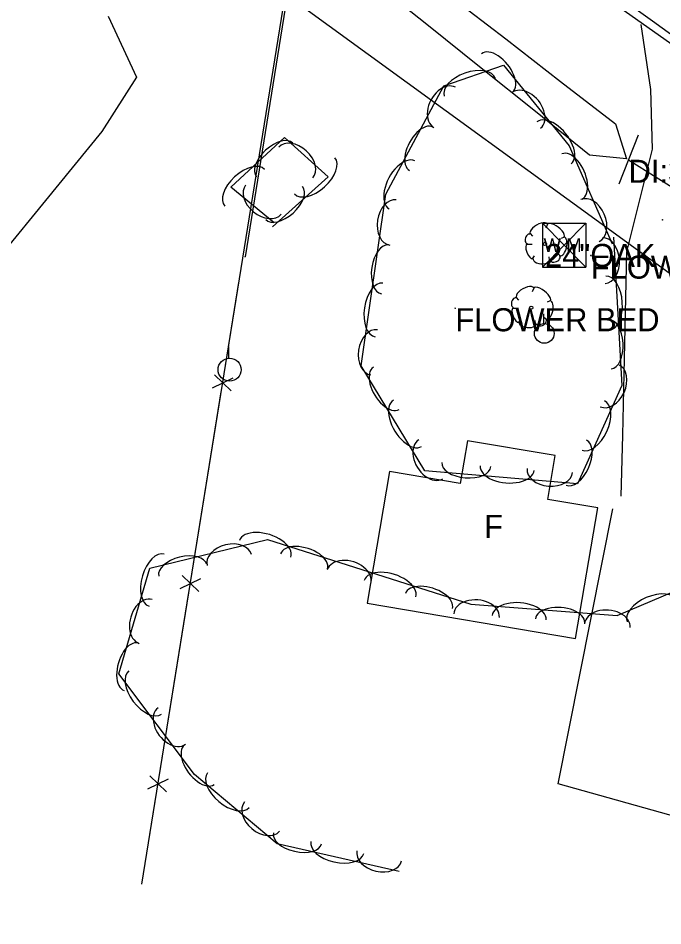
# Model space of a CAD drawing. Extents: x 1441650 to 1491889, y 345904 to 358319.
# Drawn here: x 1444980.2 to 1445119.8, y 354726 to 354922.6 of the extents above; entities that cross this region are included whole.
import ezdxf

# ---------------------------------------------------------------- set-up
doc = ezdxf.new("R2010")
doc.units = 0
for name, color, linetype in [('S_BUILDING', 7, 'Continuous'), ('S_BUILDING_ANNOT', 7, 'Continuous'), ('S_CROSS_DRAIN', 7, 'Continuous'), ('S_CROSS_DRAIN_ANNOT', 7, 'Continuous'), ('S_DITCHLINE', 7, 'Continuous'), ('S_DRG_PT_SYM', 7, 'Continuous'), ('S_EDGE_PAVEMENT', 7, 'Continuous'), ('S_FENCE', 7, 'Continuous'), ('S_GRAVEL_ROAD', 7, 'Continuous'), ('S_HEADWALL', 7, 'Continuous'), ('S_MSC_PT_SYM', 7, 'Continuous'), ('S_PARKING', 7, 'Continuous'), ('S_SHOULDER', 7, 'Continuous'), ('S_SURVEY_TEXT_ANNOT', 7, 'Continuous'), ('S_TREE', 7, 'Continuous'), ('S_TREE_ANNOT', 7, 'Continuous'), ('S_UTILITY_POLE', 7, 'Continuous'), ('S_WATER_UTILITIES', 7, 'Continuous')]:
    doc.layers.add(name, color=color, linetype=linetype)

msp = doc.modelspace()

# ---------------------------------------------------------------- linework, layer by layer
at = {"layer": 'S_BUILDING'}
msp.add_lwpolyline([(1445055.73, 354795.89), (1445100.88, 354788.24), (1445105.67, 354816.5), (1445094.84, 354818.33), (1445096.45, 354827.85), (1445077.43, 354831.07), (1445075.86, 354821.83), (1445060.56, 354824.42)], close=True, dxfattribs=at)
at = {"layer": 'S_CROSS_DRAIN'}
msp.add_line((1445112.33, 354891.94), (1445133.79, 354878.46), dxfattribs=at)
at = {"layer": 'S_DITCHLINE'}
msp.add_lwpolyline([(1445005.46, 354969.81), (1445018.13, 354968.56), (1445029.08, 354960.54), (1445040.03, 354952.52), (1445050.98, 354944.51), (1445061.93, 354936.49), (1445073.83, 354927.31), (1445085.73, 354918.12), (1445097.63, 354908.93), (1445109.52, 354899.75), (1445111.86, 354892.16), (1445103.9, 354892.94), (1445092.16, 354902.36), (1445080.42, 354911.79), (1445068.67, 354921.21), (1445056.93, 354930.63), (1445044.62, 354939.04), (1445032.31, 354947.45), (1445020, 354955.86), (1445007.69, 354964.27)], close=True, dxfattribs=at)
at = {"layer": 'S_DRG_PT_SYM'}
msp.add_lwpolyline([(1445112.33, 354891.94), (1445112.33, 354891.99), (1445112.33, 354891.94), (1445112.28, 354891.94), (1445112.33, 354891.94), (1445112.33, 354891.89), (1445112.33, 354891.94), (1445112.38, 354891.94)], dxfattribs=at)
at = {"layer": 'S_EDGE_PAVEMENT'}
msp.add_lwpolyline([(1445104.48, 354931.44), (1445117.54, 354922.02), (1445130.6, 354912.6), (1445144.39, 354902.99), (1445158.18, 354893.39), (1445171.35, 354884.38), (1445184.53, 354875.37), (1445198.09, 354866.37), (1445211.64, 354857.38), (1445224.35, 354849.14), (1445237.06, 354840.89), (1445251.76, 354831.71), (1445266.45, 354822.53), (1445278.03, 354815.47), (1445289.61, 354808.41)], dxfattribs=at)
at = {"layer": 'S_FENCE'}
for p, q in [((1445038.73, 354929.41), (1445029.31, 354870.93)), ((1445026.27, 354841.86), (1445022.68, 354845.34)), ((1445022.23, 354842.51), (1445026.72, 354844.69)), ((1445019.27, 354798.42), (1445015.68, 354801.9)), ((1445015.23, 354799.07), (1445019.73, 354801.25)), ((1445008.23, 354755.63), (1445012.73, 354757.81)), ((1445012.27, 354754.98), (1445008.68, 354758.46))]:
    msp.add_line(p, q, dxfattribs=at)
for points in [[(1445006.98, 354735), (1445038.28, 354929.3), (1444995.84, 354965.72)], [(1445024.79, 354845.58), (1445027.98, 354865.32)], [(1445020.98, 354821.88), (1445024.16, 354841.63)], [(1445017.79, 354802.14), (1445020.98, 354821.88)], [(1445013.98, 354778.44), (1445017.16, 354798.19)], [(1445010.8, 354758.69), (1445013.98, 354778.44)], [(1445006.98, 354735), (1445010.16, 354754.74)]]:
    msp.add_lwpolyline(points, dxfattribs=at)
at = {"layer": 'S_GRAVEL_ROAD'}
msp.add_lwpolyline([(1445115.02, 354921.26), (1445117.08, 354907.14), (1445117.45, 354894.22), (1445111.91, 354872.02), (1445111.61, 354858.78), (1445111.3, 354845.54), (1445110.99, 354832.3), (1445110.69, 354819.06)], dxfattribs=at)
at = {"layer": 'S_HEADWALL'}
msp.add_lwpolyline([(1445114.43, 354897.29), (1445110.26, 354886.62)], dxfattribs=at)
at = {"layer": 'S_MSC_PT_SYM'}
for points in [[(1445119.65, 354878.93), (1445119.65, 354878.98), (1445119.65, 354878.93), (1445119.6, 354878.93), (1445119.65, 354878.93), (1445119.65, 354878.88), (1445119.65, 354878.93), (1445119.7, 354878.93)], [(1445029.31, 354870.93), (1445029.31, 354870.98), (1445029.31, 354870.93), (1445029.26, 354870.93), (1445029.31, 354870.93), (1445029.31, 354870.88), (1445029.31, 354870.93), (1445029.36, 354870.93)], [(1445104.15, 354871.18), (1445104.15, 354871.23), (1445104.15, 354871.18), (1445104.1, 354871.18), (1445104.15, 354871.18), (1445104.15, 354871.13), (1445104.15, 354871.18), (1445104.2, 354871.18)], [(1445074.83, 354859.78), (1445074.83, 354859.83), (1445074.83, 354859.78), (1445074.78, 354859.78), (1445074.83, 354859.78), (1445074.83, 354859.73), (1445074.83, 354859.78), (1445074.88, 354859.78)]]:
    msp.add_lwpolyline(points, dxfattribs=at)
at = {"layer": 'S_PARKING'}
for points in [[(1444999.65, 354923.06), (1445005.79, 354909.82), (1444998.31, 354898.06), (1444964.51, 354856.77), (1444945.11, 354827.14), (1444930.71, 354797.81)], [(1445126.52, 354815.76), (1445124.68, 354754.11), (1445124.67, 354749.01), (1445097.1, 354756.74), (1445108.92, 354816.29)]]:
    msp.add_lwpolyline(points, dxfattribs=at)
at = {"layer": 'S_SHOULDER'}
msp.add_lwpolyline([(1445103.05, 354930.2), (1445116.32, 354920.82), (1445129.59, 354911.44), (1445143.44, 354901.68), (1445157.3, 354891.92), (1445170.43, 354883.05), (1445183.57, 354874.18), (1445197.06, 354865.12), (1445210.55, 354856.07), (1445223.33, 354847.89), (1445236.12, 354839.71), (1445250.59, 354830.39), (1445265.05, 354821.07), (1445276.89, 354813.98), (1445288.72, 354806.89)], dxfattribs=at)
at = {"layer": 'S_TREE'}
for p, q in [((1445094.8, 354877.96), (1445094.42, 354877.1)), ((1445091.01, 354875.94), (1445091.51, 354875.36)), ((1445098.37, 354875.17), (1445097.71, 354874.9)), ((1445090.35, 354873.62), (1445091.47, 354873.62)), ((1445091.51, 354870.44), (1445091.97, 354871.14)), ((1445095.19, 354870.17), (1445095.11, 354870.94)), ((1445097.59, 354871.06), (1445097.13, 354871.49)), ((1445091.82, 354864.14), (1445091.43, 354863.29)), ((1445088.02, 354862.12), (1445088.53, 354861.54)), ((1445095.39, 354861.35), (1445094.73, 354861.08)), ((1445087.36, 354859.8), (1445088.49, 354859.8)), ((1445088.53, 354856.62), (1445088.99, 354857.32)), ((1445092.21, 354856.35), (1445092.13, 354857.12)), ((1445094.61, 354857.24), (1445094.15, 354857.67))]:
    msp.add_line(p, q, dxfattribs=at)
for points in [[(1445109.05, 354875.17), (1445110.91, 354843.01), (1445101.26, 354821.71), (1445068.25, 354824.55), (1445054.43, 354847.27), (1445059.82, 354884.49), (1445072.33, 354907.95), (1445085.26, 354912.43), (1445099.47, 354894.94), (1445108.78, 354873.74)], [(1445035.58, 354878.3), (1445026.23, 354885.99), (1445037.86, 354896.75), (1445047.27, 354888.22), (1445035.25, 354877.43)], [(1445062.66, 354737.7), (1445036.25, 354743.75), (1445018.34, 354758.77), (1445002, 354780.57), (1445008.72, 354803.48), (1445034.19, 354809.69), (1445078.19, 354795.67), (1445109.88, 354793.21), (1445132.32, 354802.76), (1445141.03, 354825.37), (1445149.69, 354845.03), (1445168.23, 354849.09), (1445178.41, 354829.92), (1445171.6, 354792.55), (1445175.47, 354753.75), (1445190.97, 354727.66), (1445216.54, 354694.19), (1445235.93, 354674.69), (1445255.34, 354667.34), (1445272.22, 354672.85), (1445290.88, 354695.22)]]:
    msp.add_lwpolyline(points, dxfattribs=at)
for centre in [(1445094.24, 354873.71), (1445091.26, 354859.89)]:
    msp.add_circle(centre, 0.341, dxfattribs=at)
for centre, major_axis, ratio, start_param, end_param in [((1445083.88, 354910.77), (-3.37, 4.15), 0.540791, 3.141474, 6.283067), ((1445077.97, 354907.66), (-5.54, -1.92), 0.550022, 3.141593, 6.283185), ((1445072.54, 354903.28), (-2.33, -4.37), 0.685178, 3.141644, 6.283237), ((1445090.17, 354902.61), (-3.13, 3.84), 0.685427, 3.141392, 6.282985), ((1445096.21, 354895.59), (-3.7, 4.55), 0.550173, 3.14147, 6.283063), ((1445067.46, 354894.31), (-2.52, -4.72), 0.540595, 3.141623, 6.283216), ((1445035.73, 354891.89), (-3.92, -3.63), 0.540699, 3.141593, 6.283185), ((1445040.29, 354891.34), (-3.67, 3.33), 0.685311, 3.141593, 6.283185), ((1445044.38, 354888.47), (4.37, 3.92), 0.55008, 3.141593, 6.283185), ((1445100.07, 354888.31), (-2.15, 4.9), 0.540659, 3.14158, 6.283173), ((1445029.22, 354885.87), (-4.31, -3.98), 0.55008, 3.141593, 6.283185), ((1445063.29, 354886.49), (-2.76, -5.18), 0.549973, 3.141624, 6.283217), ((1445033.27, 354883.29), (3.83, -3.15), 0.685418, 3.141593, 6.283185), ((1445037.78, 354882.55), (3.98, 3.57), 0.540699, 3.141593, 6.283185), ((1445061.34, 354878.34), (-0.71, -4.9), 0.685192, 3.141598, 6.28319), ((1445103.97, 354878.78), (-1.99, 4.54), 0.685259, 3.141572, 6.283164), ((1445092.91, 354876.91), (1.86, 1.08), 0.471018, 0, 3.141593), ((1445096.56, 354876.59), (-1.81, 1.36), 0.405113, 3.141593, 6.283186), ((1445090.67, 354874.8), (0.31, 1.03), 0.646762, 0, 3.141593), ((1445097.92, 354873.18), (0.46, 2.04), 0.482994, 3.141593, 6.283185), ((1445106.96, 354870.09), (-0.29, 4.95), 0.685212, 3.141593, 6.283185), ((1445059.6, 354868.19), (-0.77, -5.29), 0.540605, 3.141596, 6.283188), ((1445090.98, 354872.15), (-0.61, 1.6), 0.420543, 6.283185, 9.424777), ((1445096.4, 354870.66), (1.09, 0.46), 0.711534, 3.141592, 6.283185), ((1445093.44, 354870.37), (-1.83, 0.19), 0.529943, 0, 3.141593), ((1445107.76, 354860.86), (-0.34, 5.86), 0.550001, 3.141593, 6.283185), ((1445058.33, 354859.41), (-0.84, -5.81), 0.549984, 3.141596, 6.283188), ((1445089.93, 354863.09), (1.86, 1.08), 0.471018, 0, 3.141593), ((1445093.58, 354862.77), (-1.81, 1.36), 0.405113, 3.141593, 6.283186), ((1445087.69, 354860.98), (0.31, 1.03), 0.646762, 0, 3.141593), ((1445094.94, 354859.36), (0.46, 2.04), 0.482994, 3.141593, 6.283185), ((1445088, 354858.33), (-0.61, 1.6), 0.420543, 6.283185, 9.424777), ((1445093.41, 354856.84), (1.09, 0.46), 0.711534, 3.141592, 6.283185), ((1445108.27, 354852.01), (-0.31, 5.34), 0.540622, 3.141593, 6.283185), ((1445057.26, 354850.21), (-0.71, -4.9), 0.685192, 3.141598, 6.28319), ((1445090.46, 354856.55), (-1.83, 0.19), 0.529943, 0, 3.141593), ((1445108.27, 354842.93), (2.05, 4.51), 0.685177, 3.141593, 6.283185), ((1445059.87, 354842.41), (2.78, -4.57), 0.540674, 3.141617, 6.28321), ((1445064.48, 354834.83), (3.05, -5.01), 0.550054, 3.141618, 6.283211), ((1445104.68, 354834.39), (2.42, 5.34), 0.549973, 3.141593, 6.283185), ((1445069.51, 354827.05), (2.58, -4.23), 0.685279, 3.141634, 6.283227), ((1445101.02, 354826.31), (2.21, 4.87), 0.540594, 3.141593, 6.283185), ((1445077.21, 354825.91), (5.32, -0.46), 0.540915, 3.141421, 6.283013), ((1445086.04, 354825.15), (5.84, -0.5), 0.550299, 3.141415, 6.283008), ((1445095.28, 354824.61), (4.93, -0.42), 0.685584, 3.141302, 6.282894), ((1445033.66, 354807.64), (-5.58, 1.78), 0.551399, 3.142135, 6.283728), ((1445025.88, 354805.21), (-4.81, -1.18), 0.685173, 3.141593, 6.283185), ((1445042.09, 354804.95), (-5.08, 1.62), 0.541996, 3.142118, 6.283711), ((1445010.17, 354800.87), (-1.65, -5.63), 0.549944, 3.141576, 6.283168), ((1445015.81, 354803.02), (-5.19, -1.27), 0.540591, 3.141593, 6.283185), ((1445051.8, 354801.58), (-4.71, 1.5), 0.686955, 3.142484, 6.284077), ((1445060.68, 354799.02), (-5.58, 1.78), 0.551399, 3.142135, 6.283728), ((1445069.11, 354796.34), (-5.08, 1.62), 0.541996, 3.142118, 6.283711), ((1445117.44, 354794.12), (-5.4, -2.3), 0.549946, 3.141593, 6.283185), ((1445007.81, 354791.91), (-1.4, -4.75), 0.685142, 3.141565, 6.283158), ((1445079.42, 354793.18), (-4.94, 0.39), 0.685551, 3.142167, 6.28376), ((1445088.67, 354792.73), (-5.85, 0.46), 0.550273, 3.141943, 6.283536), ((1445097.51, 354792.04), (-5.33, 0.41), 0.540889, 3.141932, 6.283525), ((1445107.75, 354790.98), (-4.94, 0.39), 0.685551, 3.142167, 6.28376), ((1445004.66, 354782.1), (-1.51, -5.13), 0.540566, 3.141576, 6.283169), ((1445007.68, 354776.52), (3.52, -4.69), 0.550079, 3.141574, 6.283166), ((1445013.44, 354769.27), (2.97, -3.96), 0.68531, 3.141561, 6.283154), ((1445019.41, 354760.87), (3.21, -4.28), 0.540698, 3.141574, 6.283167), ((1445025.7, 354755.37), (4.5, -3.77), 0.55008, 3.141593, 6.283185), ((1445032.97, 354749.62), (3.8, -3.18), 0.685311, 3.141593, 6.283185), ((1445040.64, 354744.93), (5.21, -1.19), 0.540663, 3.141593, 6.283185), ((1445049.28, 354742.95), (5.72, -1.31), 0.550043, 3.141593, 6.283185), ((1445058.37, 354741.13), (4.83, -1.11), 0.685264, 3.141593, 6.283185)]:
    msp.add_ellipse(centre, major_axis=major_axis, ratio=ratio, start_param=start_param, end_param=end_param, dxfattribs=at)
at = {"layer": 'S_UTILITY_POLE'}
for p, q in [((1445093.97, 354856.46), (1445093.97, 354858.57)), ((1445025.82, 354848.98), (1445025.82, 354851.46))]:
    msp.add_line(p, q, dxfattribs=at)
for centre, radius in [((1445094.09, 354854.32), 2.13), ((1445025.96, 354846.46), 2.5)]:
    msp.add_circle(centre, radius, dxfattribs=at)
at = {"layer": 'S_WATER_UTILITIES'}
for p, q in [((1444933.86, 355003.67), (1445212.56, 354800.91)), ((1445093.73, 354878.19), (1445103.07, 354878.19)), ((1445093.73, 354878.19), (1445093.73, 354868.69)), ((1445093.73, 354878.19), (1445103.07, 354868.69)), ((1445103.07, 354878.19), (1445093.73, 354868.69)), ((1445103.07, 354878.19), (1445103.07, 354868.69)), ((1445093.73, 354868.69), (1445103.07, 354868.69))]:
    msp.add_line(p, q, dxfattribs=at)

# ---------------------------------------------------------------- texts
at = {"layer": 'S_BUILDING_ANNOT'}
msp.add_text('F', height=5, dxfattribs=at).set_placement((1445081.08, 354810))
at = {"layer": 'S_CROSS_DRAIN_ANNOT'}
msp.add_text('DI:36" CN:40% TY:CMP', height=5, dxfattribs=at).set_placement((1445112.33, 354886.94))
at = {"layer": 'S_SURVEY_TEXT_ANNOT'}
for p in [(1445104.15, 354866.18), (1445074.83, 354854.78)]:
    msp.add_text('FLOWER BED', height=5, dxfattribs=at).set_placement(p)
at = {"layer": 'S_TREE_ANNOT'}
msp.add_text('24"OAK', height=5, dxfattribs=at).set_placement((1445094.24, 354868.71))
at = {"layer": 'S_WATER_UTILITIES'}
msp.add_text('W M', height=3, rotation=360, dxfattribs=at).set_placement((1445093.93, 354871.95))

doc.saveas('drawing.dxf')
